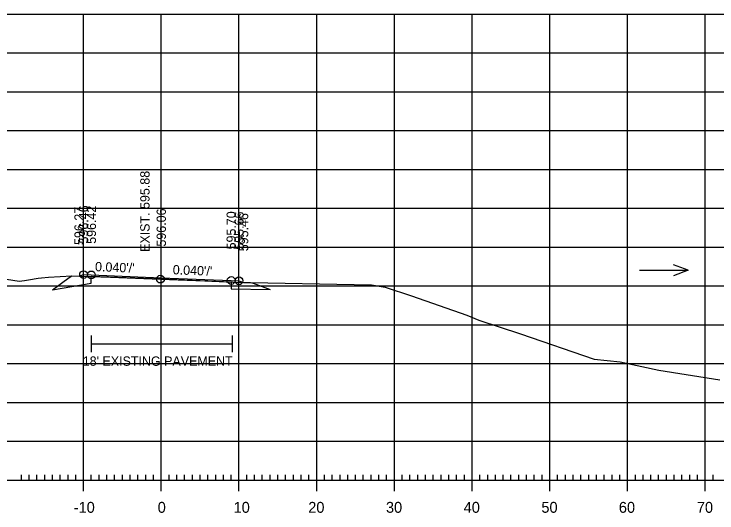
# Model space of a CAD drawing. Extents: x 961436 to 1372525, y 380079 to 2027791.
# Drawn here: x 1370614.9 to 1370705.3, y 380606.5 to 380670.7 of the extents above; entities that cross this region are included whole.
import ezdxf

# ---------------------------------------------------------------- set-up
doc = ezdxf.new("R2010")
doc.units = 0
for name, color, linetype in [('R_Alt Surface', 7, 'Continuous'), ('R_Axis', 7, 'Continuous'), ('R_Axis Annot', 7, 'Continuous'), ('R_Drive', 7, 'Continuous'), ('R_Exist Surface', 7, 'Continuous'), ('R_Fin Surface', 7, 'Continuous'), ('R_Fin Surface Annot', 7, 'Continuous'), ('R_Grid', 7, 'Continuous'), ('R_No Plot', 7, 'Continuous'), ('R_Water Annot', 7, 'Continuous'), ('R_Xsect Elev', 7, 'Continuous')]:
    doc.layers.add(name, color=color, linetype=linetype)

msp = doc.modelspace()

# ---------------------------------------------------------------- linework, layer by layer
at = {"layer": 'R_Alt Surface'}
msp.add_lwpolyline([(1370619.812, 380635.255), (1370624.812, 380636.075), (1370624.802, 380636.074), (1370624.812, 380636.991), (1370633.812, 380636.631), (1370642.812, 380636.271), (1370642.822, 380635.354), (1370642.812, 380635.355), (1370647.812, 380635.288)], dxfattribs=at)
at = {"layer": 'R_Axis'}
for p, q in [((1370615.812, 380610.735), (1370615.812, 380611.435)), ((1370616.812, 380610.735), (1370616.812, 380611.435)), ((1370617.812, 380610.735), (1370617.812, 380611.435)), ((1370618.812, 380610.735), (1370618.812, 380611.435)), ((1370619.812, 380610.735), (1370619.812, 380611.435)), ((1370620.812, 380610.735), (1370620.812, 380611.435)), ((1370621.812, 380610.735), (1370621.812, 380611.435)), ((1370622.812, 380610.735), (1370622.812, 380611.435)), ((1370623.812, 380609.335), (1370623.812, 380612.135)), ((1370624.812, 380610.735), (1370624.812, 380611.435)), ((1370625.812, 380610.735), (1370625.812, 380611.435)), ((1370626.812, 380610.735), (1370626.812, 380611.435)), ((1370627.812, 380610.735), (1370627.812, 380611.435)), ((1370628.812, 380610.735), (1370628.812, 380611.435)), ((1370629.812, 380610.735), (1370629.812, 380611.435)), ((1370630.812, 380610.735), (1370630.812, 380611.435)), ((1370631.812, 380610.735), (1370631.812, 380611.435)), ((1370632.812, 380610.735), (1370632.812, 380611.435)), ((1370633.812, 380609.335), (1370633.812, 380612.135)), ((1370634.812, 380610.735), (1370634.812, 380611.435)), ((1370635.812, 380610.735), (1370635.812, 380611.435)), ((1370636.812, 380610.735), (1370636.812, 380611.435)), ((1370637.812, 380610.735), (1370637.812, 380611.435)), ((1370638.812, 380610.735), (1370638.812, 380611.435)), ((1370639.812, 380610.735), (1370639.812, 380611.435)), ((1370640.812, 380610.735), (1370640.812, 380611.435)), ((1370641.812, 380610.735), (1370641.812, 380611.435)), ((1370642.812, 380610.735), (1370642.812, 380611.435)), ((1370643.812, 380609.335), (1370643.812, 380612.135)), ((1370644.812, 380610.735), (1370644.812, 380611.435)), ((1370645.812, 380610.735), (1370645.812, 380611.435)), ((1370646.812, 380610.735), (1370646.812, 380611.435)), ((1370647.812, 380610.735), (1370647.812, 380611.435)), ((1370648.812, 380610.735), (1370648.812, 380611.435)), ((1370649.812, 380610.735), (1370649.812, 380611.435)), ((1370650.812, 380610.735), (1370650.812, 380611.435)), ((1370651.812, 380610.735), (1370651.812, 380611.435)), ((1370652.812, 380610.735), (1370652.812, 380611.435)), ((1370653.812, 380609.335), (1370653.812, 380612.135)), ((1370654.812, 380610.735), (1370654.812, 380611.435)), ((1370655.812, 380610.735), (1370655.812, 380611.435)), ((1370656.812, 380610.735), (1370656.812, 380611.435)), ((1370657.812, 380610.735), (1370657.812, 380611.435)), ((1370658.812, 380610.735), (1370658.812, 380611.435)), ((1370659.812, 380610.735), (1370659.812, 380611.435)), ((1370660.812, 380610.735), (1370660.812, 380611.435)), ((1370661.812, 380610.735), (1370661.812, 380611.435)), ((1370662.812, 380610.735), (1370662.812, 380611.435)), ((1370663.812, 380609.335), (1370663.812, 380612.135)), ((1370664.812, 380610.735), (1370664.812, 380611.435)), ((1370665.812, 380610.735), (1370665.812, 380611.435)), ((1370666.812, 380610.735), (1370666.812, 380611.435)), ((1370667.812, 380610.735), (1370667.812, 380611.435)), ((1370668.812, 380610.735), (1370668.812, 380611.435)), ((1370669.812, 380610.735), (1370669.812, 380611.435)), ((1370670.812, 380610.735), (1370670.812, 380611.435)), ((1370671.812, 380610.735), (1370671.812, 380611.435)), ((1370672.812, 380610.735), (1370672.812, 380611.435)), ((1370673.812, 380609.335), (1370673.812, 380612.135)), ((1370674.812, 380610.735), (1370674.812, 380611.435)), ((1370675.812, 380610.735), (1370675.812, 380611.435)), ((1370676.812, 380610.735), (1370676.812, 380611.435)), ((1370677.812, 380610.735), (1370677.812, 380611.435)), ((1370678.812, 380610.735), (1370678.812, 380611.435)), ((1370679.812, 380610.735), (1370679.812, 380611.435)), ((1370680.812, 380610.735), (1370680.812, 380611.435)), ((1370681.812, 380610.735), (1370681.812, 380611.435)), ((1370682.812, 380610.735), (1370682.812, 380611.435)), ((1370683.812, 380609.335), (1370683.812, 380612.135)), ((1370684.812, 380610.735), (1370684.812, 380611.435)), ((1370685.812, 380610.735), (1370685.812, 380611.435)), ((1370686.812, 380610.735), (1370686.812, 380611.435)), ((1370687.812, 380610.735), (1370687.812, 380611.435)), ((1370688.812, 380610.735), (1370688.812, 380611.435)), ((1370689.812, 380610.735), (1370689.812, 380611.435)), ((1370690.812, 380610.735), (1370690.812, 380611.435)), ((1370691.812, 380610.735), (1370691.812, 380611.435)), ((1370692.812, 380610.735), (1370692.812, 380611.435)), ((1370693.812, 380609.335), (1370693.812, 380612.135)), ((1370694.812, 380610.735), (1370694.812, 380611.435)), ((1370695.812, 380610.735), (1370695.812, 380611.435)), ((1370696.812, 380610.735), (1370696.812, 380611.435)), ((1370697.812, 380610.735), (1370697.812, 380611.435)), ((1370698.812, 380610.735), (1370698.812, 380611.435)), ((1370699.812, 380610.735), (1370699.812, 380611.435)), ((1370700.812, 380610.735), (1370700.812, 380611.435)), ((1370701.812, 380610.735), (1370701.812, 380611.435)), ((1370702.812, 380610.735), (1370702.812, 380611.435)), ((1370703.812, 380609.335), (1370703.812, 380612.135)), ((1370704.812, 380610.735), (1370704.812, 380611.435)), ((1370493.812, 380610.735), (1370773.812, 380610.735))]:
    msp.add_line(p, q, dxfattribs=at)
at = {"layer": 'R_Drive'}
for p, q in [((1370624.798, 380629.344), (1370624.798, 380627.208)), ((1370642.926, 380629.344), (1370642.926, 380627.208)), ((1370624.798, 380628.276), (1370642.926, 380628.276))]:
    msp.add_line(p, q, dxfattribs=at)
at = {"layer": 'R_Exist Surface'}
msp.add_lwpolyline([(1370613.88, 380636.59), (1370615.543, 380636.342), (1370616.212, 380636.44), (1370616.738, 380636.539), (1370617.974, 380636.74), (1370618.405, 380636.797), (1370619.286, 380636.868), (1370622.31, 380637.039), (1370627.287, 380636.868), (1370633.707, 380636.615), (1370639.423, 380636.396), (1370643.072, 380636.226), (1370660.878, 380635.879), (1370662.61, 380635.571), (1370665.991, 380634.477), (1370673.14, 380631.964), (1370674.667, 380631.343), (1370680.041, 380629.573), (1370689.507, 380626.291), (1370692.843, 380625.956), (1370697.85, 380624.907), (1370705.688, 380623.638)], dxfattribs=at)
at = {"layer": 'R_Fin Surface'}
msp.add_lwpolyline([(1370619.812, 380635.255), (1370621.94, 380636.828), (1370622.286, 380637.03), (1370623.24, 380637.007), (1370623.812, 380637.198), (1370624.812, 380637.158), (1370633.812, 380636.798), (1370642.812, 380636.438), (1370643.812, 380636.398), (1370644.407, 380636.2), (1370645.263, 380636.183), (1370645.619, 380636.075), (1370647.812, 380635.288)], dxfattribs=at)
at = {"layer": 'R_Grid'}
for p, q in [((1370493.812, 380670.735), (1370773.812, 380670.735)), ((1370623.812, 380610.735), (1370623.812, 380670.735)), ((1370633.812, 380610.735), (1370633.812, 380670.735)), ((1370643.812, 380610.735), (1370643.812, 380670.735)), ((1370653.812, 380610.735), (1370653.812, 380670.735)), ((1370663.812, 380610.735), (1370663.812, 380670.735)), ((1370673.812, 380610.735), (1370673.812, 380670.735)), ((1370683.812, 380610.735), (1370683.812, 380670.735)), ((1370693.812, 380610.735), (1370693.812, 380670.735)), ((1370703.812, 380610.735), (1370703.812, 380670.735)), ((1370493.812, 380665.735), (1370773.812, 380665.735)), ((1370493.812, 380660.735), (1370773.812, 380660.735)), ((1370493.812, 380655.735), (1370773.812, 380655.735)), ((1370493.812, 380650.735), (1370773.812, 380650.735)), ((1370493.812, 380645.735), (1370773.812, 380645.735)), ((1370493.812, 380640.735), (1370773.812, 380640.735)), ((1370493.812, 380635.735), (1370773.812, 380635.735)), ((1370493.812, 380630.735), (1370773.812, 380630.735)), ((1370493.812, 380625.735), (1370773.812, 380625.735)), ((1370493.812, 380620.735), (1370773.812, 380620.735)), ((1370493.812, 380615.735), (1370773.812, 380615.735)), ((1370493.812, 380610.735), (1370773.812, 380610.735))]:
    msp.add_line(p, q, dxfattribs=at)
at = {"layer": 'R_No Plot'}
for centre in [(1370623.812, 380637.198), (1370624.812, 380637.158), (1370633.707, 380636.615), (1370642.812, 380636.438), (1370643.812, 380636.398)]:
    msp.add_circle(centre, 0.5, dxfattribs=at)
at = {"layer": 'R_Water Annot'}
for p, q in [((1370701.631, 380637.746), (1370699.708, 380638.446)), ((1370695.347, 380637.746), (1370701.631, 380637.746)), ((1370701.631, 380637.746), (1370699.708, 380637.046))]:
    msp.add_line(p, q, dxfattribs=at)

# ---------------------------------------------------------------- texts
at = {"layer": 'R_Axis Annot'}
for s, p in [('-10', (1370622.55, 380606.535)), ('0', (1370633.355, 380606.535)), ('10', (1370643.123, 380606.535)), ('20', (1370652.726, 380606.535)), ('30', (1370662.726, 380606.535)), ('40', (1370672.726, 380606.535)), ('50', (1370682.726, 380606.535)), ('60', (1370692.693, 380606.535)), ('70', (1370702.726, 380606.535))]:
    msp.add_text(s, height=1.4, dxfattribs=at).set_placement(p)
at = {"layer": 'R_Fin Surface Annot'}
for s, rotation, p in [('596.27', 90, (1370623.84, 380641.007)), ('596.46', 90, (1370624.412, 380641.198)), ('596.42', 90, (1370625.412, 380641.158)), ('596.06', 90, (1370634.412, 380640.798)), ('595.70', 90, (1370643.412, 380640.438)), ('595.66', 90, (1370644.412, 380640.398)), ('595.46', 90, (1370645.007, 380640.2)), ("0.040'/'", 357.70939, (1370625.273, 380637.64)), ("0.040'/'", 357.70939, (1370635.273, 380637.24))]:
    msp.add_text(s, height=1.2, rotation=rotation, dxfattribs=at).set_placement(p)
msp.add_text("18' EXISTING PAVEMENT", height=1.2, dxfattribs=at).set_placement((1370623.707, 380625.458))
at = {"layer": 'R_Xsect Elev'}
msp.add_text('EXIST. 595.88', height=1.2, rotation=90, dxfattribs=at).set_placement((1370632.307, 380640.115))

doc.saveas('drawing.dxf')
